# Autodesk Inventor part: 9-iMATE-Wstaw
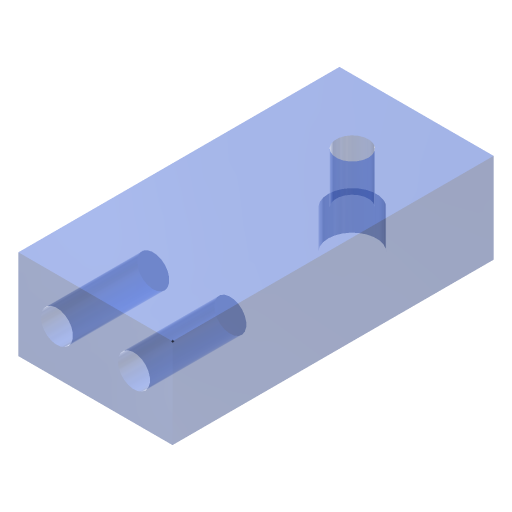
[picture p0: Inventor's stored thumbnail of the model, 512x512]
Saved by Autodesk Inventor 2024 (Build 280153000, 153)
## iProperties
Category: TEST
Company: ATC
Created: 2023-03
Part Number: 9-iMATE-Wstaw
Document SubType Name: Modeling
Designer: Andrzej Jaskulski
Manufacturer: Standard
Standards Organization: Custom
Material: AJ-PL-1
Description: Mniejsza
Density: 0.001 g/cm^3
Appearance: Niebieski (jasny)
Checked By: A.J.
Engr Approved By: Andrzej Jaskulski
Mfg Approved By: Andrzej Jaskulski
Authority: A.J.
Szer: 28,00000 mm
Wys: 48,00000 mm
Dlug: 100,00000 mm
FiStd: 10,00000 mm
m3: m3
Title: A.J.: Kurs R2024-MEP
Author: Andrzej Jaskulski
Revision Number: 1/24
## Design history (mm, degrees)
sketch "Szkic CZOŁA"
  geometry: L1 (48, 0)-(48, -28); L2 (48, -28)-(0, -28); L3 (48, 0)-(0, 0); L4 (0, 0)-(0, -28); C1 r 5 at (12, -14); C2 r 5 at (36, -14)
  constraints: 8 end point, 2 centre point, 2 horizontal, 2 vertical, 1 horizontal alignment, 1 other
  dimensions: "d1" = 28 distance of L1.start L1.end (= Szer); "d2" = 14 distance from line of C2.centre L2 (= 0.5 x d1); "d32" = 48 distance of L1.start L3.end (= Wys); "d33" = 12 distance from line of C2.centre L1 (= 0.25 x d32); "d34" = 24 distance of C1.centre C2.centre (= 0.5 x d32)
extrude "Baza" new body sketch "Szkic CZOŁA" distance "d3" = 100 (= Dlug); taper "d4" = 0 deg
extrude "Otw. w CZOLE 1" cut sketch "Szkic CZOŁA" distance "d43" = 30; taper "d44" = 0 deg
sketch "Szkic2"
  geometry: L1 (14.131, 113.514)-(2.685, 125.587); L2 (2.685, 125.587)-(14.131, 136.439); L3 (48, 0)-(0, 0) reference; 2 further points
  constraints: 4 end point, 1 midpoint, 1 perpendicular, 1 vertical alignment
  dimensions: "d101" = 80 distance from line of point (24, 80) L3
hole "Otw. z POGL." sketch "Szkic2" diameter "d75" = 10 (= FiStd); stored, may be unused: countersink angle "d79" = 90 deg, drill point angle "d81" = 0 deg; dims "d76" = 6, "d77" = 15 (= 1.5 x FiStd), "d78" = 12 (= d33), "d80" = 12 (= d33)
node "Bryła1"
node "Korpusy bryłowe"
node "Korpusy powierzchniowe"
other parameters: "FiStd" = 10 [user parameter; used in 2 equation terms], "Szer" = 28 [user parameter; used in 1 equation term], "Wys" = 48 [user parameter; used in 1 equation term], "Dlug" = 100 [user parameter; used in 1 equation term], "d102" = 0
